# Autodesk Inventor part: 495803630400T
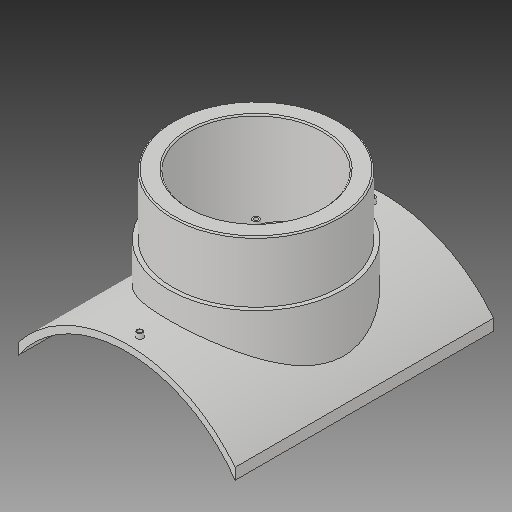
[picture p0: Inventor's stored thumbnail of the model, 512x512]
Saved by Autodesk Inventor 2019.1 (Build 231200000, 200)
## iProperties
Created: 2017-10
Part Number: 495803630400T
Material: Generic
Description: PLASSON BRANCH SADDLE 630x400
Document SubType Name: Modeling
Designer: KIM
Mass: 2754.05 g
Surface Area: 3037.44 cm^2
Volume: 2754.05 cm^3
Density: 1 g/cm^3
Appearance: Default
Author: KIM
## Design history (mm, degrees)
derived "495803.ipt"
feature "Solid1::495803.ipt"
tag "TaggingFeature1"
body "Solid1"
other parameters: "d1" = 16, "d4" = 0, "d12" = 342.1, "d13" = 14, "d14" = 279, "d16" = 5 deg, "d18" = 4, "d19" = 14, "d20" = 0, "d21" = 3, "d22" = 0, "d25" = 16, "d28" = 0, "d29" = 9.6, "d31" = 0, "d32" = 104.5, "d33" = 0, "d34" = 6.3, "d37" = 146.3, "d38" = 0, "d39" = 3.15, "H_" = 209, "x_" = 16, "D_" = 16
